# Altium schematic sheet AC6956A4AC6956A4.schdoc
size 127 x 101 mm
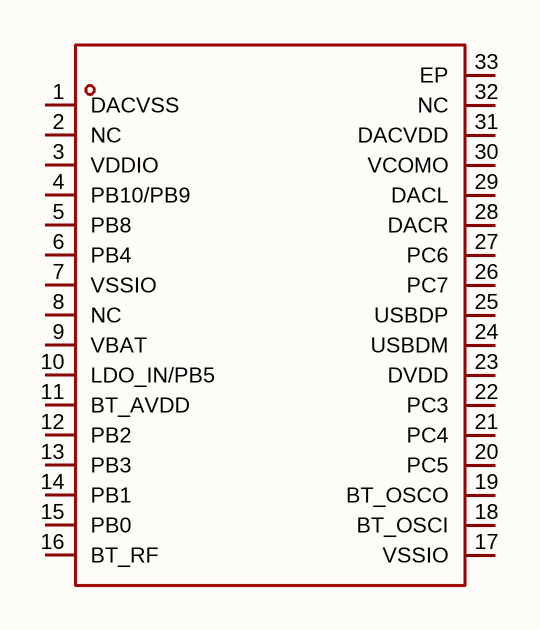
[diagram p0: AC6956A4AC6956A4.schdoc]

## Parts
U?  ac6956a4  [QFN-32_L4.0-W4.0-P0.40-BL-EP2.7-A]  (value not drawn)

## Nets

Not connected (* = marked no-connect by the designer): U? 1(DACVSS) 2(NC) 3(VDDIO) 4(PB10/PB9) 5(PB8) 6(PB4) 7(VSSIO) 8(NC) 9(VBAT) 10(LDO_IN/PB5) 11(BT_AVDD) 12(PB2) 13(PB3) 14(PB1) 15(PB0) 16(BT_RF) 17(VSSIO) 18(BT_OSCI) 19(BT_OSCO) 20(PC5) 21(PC4) 22(PC3) 23(DVDD) 24(USBDM) 25(USBDP) 26(PC7) 27(PC6) 28(DACR) 29(DACL) 30(VCOMO) 31(DACVDD) 32(NC) 33(EP)

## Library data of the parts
U? = ac6956a4: CPU内核:-;CPU最大主频:240MHz;CPU位数:32bit;; Manufacturer: JL(杰理); AddInBom: yes; ModelId: 62f3579202e14df58d38bb6b7ac8364e; ModelTransform: 157.559,157.559,0,0,0,0,0,0,0; CPU Maximum Speed: 240MHz; Core Size: 32bit; ADC (Bit): 16bit；10bit; DAC (Bit): 16bit; Voltage - Supply: 2V~5.5V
